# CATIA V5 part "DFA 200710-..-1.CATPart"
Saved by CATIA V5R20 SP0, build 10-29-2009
Part number: DFA 200710-..-1
Revision: ANY
Definition: UNKNOWN
Nomenclature: DFA 200710-..-1
Source: Unknown
Bounding box of the stored display mesh (mm): x -10 to 10, y 0.13 to 20.13, z -10 to 10
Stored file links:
  C:\Users\Utente\Desktop\IO LAVORO\3D X SITO CF\CUMSA\3D files FA\FA 200710-21\DFA 200710-..-1.CATPart

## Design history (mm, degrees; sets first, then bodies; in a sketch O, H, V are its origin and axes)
Body1 "Cortar-Extruir4" (main body)
  Solid1: solid without history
